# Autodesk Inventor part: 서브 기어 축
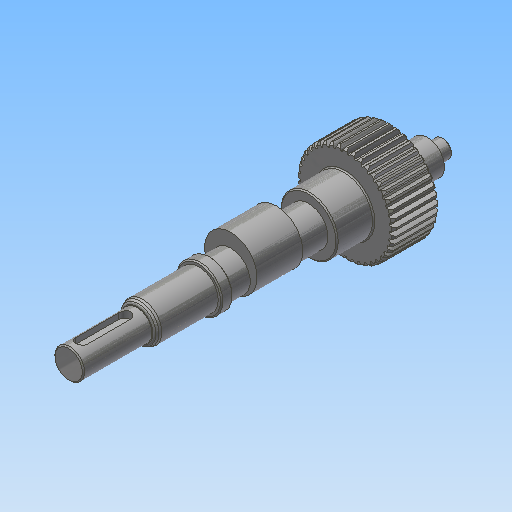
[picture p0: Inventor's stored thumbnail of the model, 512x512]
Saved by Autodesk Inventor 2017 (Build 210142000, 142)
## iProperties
Created: 2018-12
Part Number: 서브 기어 축
Material: 강철, 연강
Document SubType Name: Modeling
Designer: mduedu
Categories: <?xml version="1.0" encoding="UTF-16"?> <MemberInstance><Categories><FamilyTemplate><FamilyTemplateParameter ValueType="xs:double" Id="1" ObjectReferenceKey="da
Density: 7.86 g/cm^3
Appearance: 강철
Mass: 488.18 g
Surface Area: 153.343 cm^2
Volume: 62.1094 cm^3
Author: mduedu
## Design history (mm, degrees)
sketch "Sketch1"
  geometry: C1 r 21.3 at (0, 0)
  constraints: 1 centre point
  dimensions: "d0" = 42.6 diameter of C1 (= da_da)
extrude "Extrusion1" new body sketch "Sketch1" distance "d1" = 20 (= da_b); taper "d2" = 0 deg
workplane "Work Plane2"
sketch "Sketch2"
  geometry: C1 r 21.3 at (0, 0) reference; C2 r 20.5 at (0, 0)
  constraints: 1 centre point, 1 coincident
  dimensions: "d3" = 41 diameter of C2 (= da_dw)
feature "피치 지름" sketch "Sketch2" dims "d4" = 10, "d5" = 0
workplane "Work Plane8"
workplane "Work Plane9"
chamfer "모따기1" distance "d49" = 1; stored, may be unused: second distance "d50" = 2, angle "d51" = 45 deg
sketch "스케치3"
  geometry: C1 r 12.5 at (0, 0); 1 further point
  constraints: 1 centre point, 1 coincident
  dimensions: "d52" = 25 diameter of C1
extrude "돌출2" join sketch "스케치3" distance "d53" = 16; taper "d54" = 0 deg
sketch "스케치4"
  geometry: C1 r 8.5 at (0, 0); 1 further point
  constraints: 1 centre point, 1 coincident
  dimensions: "d55" = 17 diameter of C1
extrude "돌출3" join sketch "스케치4" distance "d56" = 105; taper "d57" = 0 deg
sketch "스케치5"
  geometry: C1 r 7.5 at (0, 0); 1 further point
  constraints: 1 centre point, 1 coincident
  dimensions: "d58" = 15 diameter of C1
extrude "돌출4" join sketch "스케치5" distance "d59" = 16; taper "d60" = 0 deg
sketch "스케치6"
  geometry: C1 r 4 at (0, 0); 1 further point
  constraints: 1 centre point, 1 coincident
  dimensions: "d61" = 8 diameter of C1
extrude "돌출5" join sketch "스케치6" distance "d62" = 7; taper "d63" = 0 deg
fillet "모깎기1" dims "d67" = 0.5
feature "스퍼 기어" dims "da_b" = 20, "da_d" = 41, "da_aw" = 31, "da_da" = 42.6, "da_df" = 39.086, "da_dw" = 41, angle "da_beta" = 0 deg, "da_lefttooth" = 0, "da_righttooth" = 0
node "작업 평면11"
sketch "스케치7"
  geometry: C1 r 11.5 at (0, 3); C2 r 8.5 at (0, 0) reference; 1 further point
  constraints: 1 centre point, 1 tangent, 1 vertical alignment
  dimensions: "d69" = 3 distance of point (0, 0) C1.centre; "d70" = 23 diameter of C1 (derived)
extrude "돌출6" join sketch "스케치7" stored distance "d71" = 20; taper "d72" = 0 deg
node "작업 평면12"
sketch "스케치8"
  geometry: C1 r 12.5 at (0, 0) reference; C2 r 10 at (0, 0); 1 further point
  constraints: 1 centre point, 1 coincident
  dimensions: "d110" = 20 diameter of C2
extrude "돌출7" join sketch "스케치8" distance "d74" = 5; taper "d75" = 0 deg
sketch "스케치14"
  geometry: L1 (-11.5, 111)-(-6.5, 111); L2 (-6.5, 111)-(-6.5, 141); L3 (-6.5, 141)-(-11.5, 141); L4 (-11.5, 141)-(-11.5, 111); L5 (8.5, 141)-(-8.5, 141) reference; L6 (0, 0)-(0, 141)
  constraints: 10 end point, 2 parallel, 1 collinear, 1 horizontal, 1 midpoint, 1 perpendicular
  dimensions: "d92" = 30 distance between parallel lines of L1 L5; "d93" = 13 diameter of L2 L6; "d95" = 5 distance of L2.end L3.end
revolve "회전2" sketch "스케치14" stored, may be unused: angle "d96" = 90 deg
chamfer "모따기4" distance "d97" = 0.5; stored, may be unused: second distance "d98" = 2, angle "d99" = 45 deg
revolve "회전1" stored, may be unused: angle "d82" = 90 deg
sketch "스케치10"
  geometry: L1 (-6.5, 117.5)-(-5, 116) reference; L2 (-6.5, 114.5)-(-5, 116) reference; 2 further points
  constraints: 1 coincident
node "작업점1"
node "작업 평면13"
sketch "스케치11"
  geometry: L1 (-2.5, 9.5)-(-2.5, -9.5); L2 (2.5, -9.5)-(2.5, 9.5); L3 (-6, 15)-(6, 15) reference; A1 r 2.5 centre (0, 9.5) between (2.5, 9.5) and (-2.5, 9.5); A2 r 2.5 centre (0, -9.5) between (-2.5, -9.5) and (2.5, -9.5); 1 further point
  constraints: 4 end point, 4 point on circle, 4 tangent, 2 centre point, 2 vertical alignment, 1 parallel
  dimensions: "d84" = 24 dimension on A2 A1; "d85" = 5 distance between parallel lines of L1 L2; "d108" = 3 distance edge to line of A1 L3
extrude "돌출8" cut sketch "스케치11" distance "d86" = 3; taper "d87" = 0 deg
sketch "스케치12" dims "d88" = 32
  geometry: C1 r 0.5 at (0, -16); 2 further points
  constraints: 2 vertical alignment, 1 centre point, 1 coincident, 2 other
  dimensions: "d89" = 1 diameter of C1
extrude "돌출9" join sketch "스케치12" distance "d90" = 0.3; taper "d91" = 0 deg
sketch "스케치13"
  geometry: C1 r 11.5 at (0, 3) reference; 1 further point
  node "절단 모서리 투영1"
sketch "스케치15"
  geometry: L1 (-8.5, 109.181)-(-7.45, 111); L2 (-8.5, 111)-(8.5, 111) reference; L3 (-8.5, 84)-(-8.5, 111) reference; L4 (0, 0)-(0, 111); L5 (-7.45, 111)-(-8.5, 111); L6 (-8.5, 109.181)-(-8.5, 111)
  constraints: 8 end point, 2 collinear, 2 point on line, 1 midpoint
  dimensions: "d103" = 14.9 diameter of L1.end L4; "d104" = 30 deg angle of L3 L1
revolve "회전3" sketch "스케치15" stored, may be unused: angle "d105" = 90 deg
fillet "모깎기2" dims "d106" = 2
fillet "모깎기3" dims "d107" = 1
chamfer "모따기5" distance "d112" = 0.5; stored, may be unused: second distance "d113" = 2, angle "d114" = 45 deg
body "Solid1"
body "Srf1"
node "투영된 루프1"
sketch "스케치9"
  geometry: L1 (0, 138.97)-(0, 0); L2 (-6.5, 116)-(0, 116); L3 (-6.5, 116)-(-6.5, 114.5); L4 (-6.5, 114.5)-(-5, 116); L5 (-5, 116)-(-6.5, 116); L6 (-6, 141)-(6, 141) reference
  constraints: 10 end point, 2 point on line, 1 collinear, 1 vertical
  dimensions: "d80" = 3 diameter of L3.end L2; "d100" = 25 distance between parallel lines of L6 L2; "d101" = 6.5 distance between parallel lines of L1 L3; "d102" = 45 deg angle of L4 L3
other parameters: "d16" = 31 (= da_aw), "d17" = 0, "d34" = 0.76624 (computed from da_z), "d39" = 0, "d41" = 0, "d43" = 31 (= da_aw), "d46" = 31 (= da_aw), "d47" = 0, "d48" = 0
